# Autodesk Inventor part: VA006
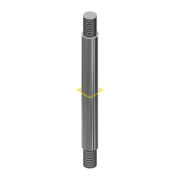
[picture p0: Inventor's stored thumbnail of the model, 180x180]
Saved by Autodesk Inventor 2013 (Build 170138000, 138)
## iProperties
Manager: P MOLLOY
Company: NUIG
Shininess: 64.0
Length Units: 11269
Angle Units: 11279
Time Units: 11290
Mass Units: 11283
Length Display Precision: 3
Angle Display Precision: 2
Compacted: True
Part Number: VA006
Document SubType Name: Modeling
Created: 2004-12
Designer: warren davies
Manufacturer: Standard
Standards Organization: Custom
Material: Stainless Steel
Mass: 60.6933 g
Surface Area: 32.9239 cm^2
Volume: 7.51155 cm^3
Density: 8.08 g/cm^3
Density: 0.0
Volumn: 0.0
Area: 0.0
PropertySet Name: Model Information
Control State: 0
Master: False
Checked Out: False
Title: CLAMPSCREW HANDLE
Subject: VICE ASSEMBLY
Author: warren davies
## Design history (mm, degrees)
sketch "Sketch1"
  geometry: C1 r 4 at (0, 0)
  constraints: 1 centre point
  dimensions: "d0" = 8 diameter of C1
extrude "Extrusion1" new body sketch "Sketch1" distance "d1" = 13; taper "d2" = 0 deg
sketch "Sketch2"
  geometry: C1 r 4 at (0, 0) reference; C2 r 5 at (0, 0)
  constraints: 1 centre point, 1 coincident
  dimensions: "d3" = 10 diameter of C2
extrude "Extrusion2" join sketch "Sketch2" distance "d4" = 79; taper "d5" = 0 deg
sketch "Sketch3"
  geometry: C1 r 5 at (0, 0) reference; C2 r 4 at (0, 0)
  constraints: 1 centre point, 1 coincident
  dimensions: "d6" = 8 diameter of C2
extrude "Extrusion3" join sketch "Sketch3" distance "d7" = 13; taper "d8" = 0 deg
thread "Thread1" dims "d9" = 10, "d10" = 0
thread "Thread2" dims "d11" = 10, "d12" = 0
workplane "Work Plane1"
body "Solid1"
